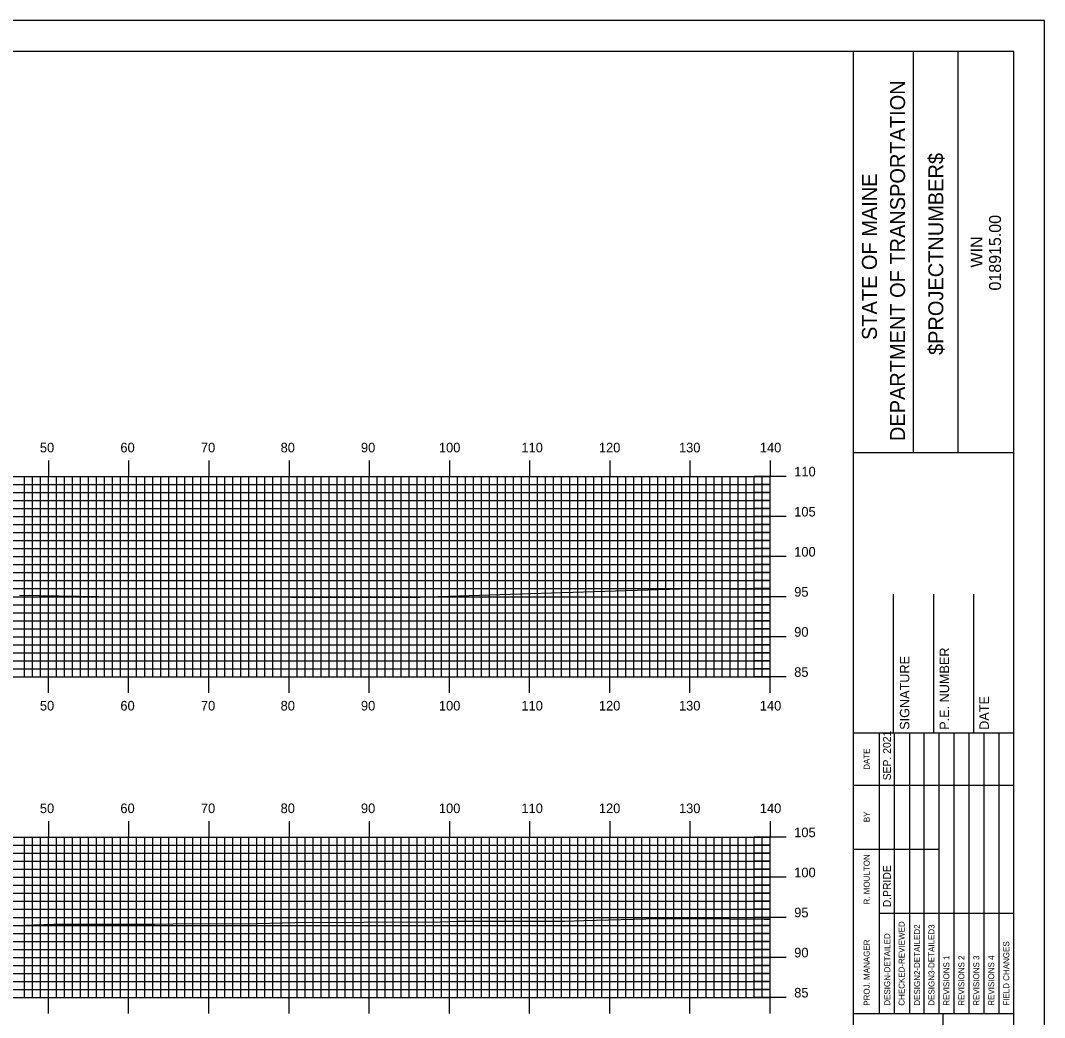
# Model space of a CAD drawing. Extents: x 1764152 to 1764495, y 442591 to 442811.
# Drawn here: x 1764364.3 to 1764492, y 442686.2 to 442810.5 of the extents above; entities that cross this region are included whole.
import ezdxf

# ---------------------------------------------------------------- set-up
doc = ezdxf.new("R2010")
doc.units = 0
for name, color, linetype in [('BORDER', 7, 'Continuous'), ('H_V ANNOTATION', 7, 'Continuous'), ('MAJOR', 7, 'Continuous'), ('MINOR', 7, 'Continuous'), ('PLOT BOUNDARY', 7, 'Continuous'), ('S_Roadway_Centerline', 7, 'Continuous')]:
    doc.layers.add(name, color=color, linetype=linetype)

msp = doc.modelspace()

# ---------------------------------------------------------------- linework, layer by layer
at = {"layer": 'BORDER'}
for p, q in [((1764468.23, 442596.67), (1764468.23, 442806.67)), ((1764475.69, 442756.66), (1764475.69, 442806.66)), ((1764481.28, 442756.66), (1764481.28, 442806.66)), ((1764468.23, 442756.65), (1764488.23, 442756.65)), ((1764473.23, 442721.67), (1764473.23, 442738.97)), ((1764478.23, 442721.67), (1764478.23, 442738.97)), ((1764483.23, 442721.67), (1764483.23, 442738.97)), ((1764468.23, 442721.67), (1764488.23, 442721.67)), ((1764468.23, 442686.67), (1764488.23, 442686.67)), ((1764479.41, 442616.67), (1764479.41, 442686.67))]:
    msp.add_line(p, q, dxfattribs=at)
msp.add_lwpolyline([(1764168.23, 442596.67), (1764488.23, 442596.67), (1764488.23, 442806.67), (1764168.23, 442806.67)], close=True, dxfattribs=at)
for points in [[(1764471.46, 442715.17), (1764471.46, 442721.67)], [(1764473.33, 442686.68), (1764473.33, 442721.67)], [(1764475.19, 442721.67), (1764475.19, 442686.68)], [(1764477.05, 442686.68), (1764477.05, 442721.67)], [(1764478.92, 442686.68), (1764478.92, 442721.67)], [(1764480.78, 442686.68), (1764480.78, 442721.67)], [(1764482.64, 442686.68), (1764482.64, 442721.67)], [(1764484.51, 442686.68), (1764484.51, 442721.67)], [(1764486.37, 442686.68), (1764486.37, 442721.67)], [(1764471.46, 442686.68), (1764471.46, 442720.26)], [(1764468.23, 442715.17), (1764488.23, 442715.17)], [(1764468.23, 442707.17), (1764471.46, 442707.17)], [(1764471.46, 442707.17), (1764478.91, 442707.17)], [(1764471.46, 442699.17), (1764488.23, 442699.17)]]:
    msp.add_lwpolyline(points, dxfattribs=at)
at = {"layer": 'MAJOR'}
for p, q in [((1764367.83, 442755.67), (1764367.83, 442753.67)), ((1764377.83, 442755.67), (1764377.83, 442753.67)), ((1764387.83, 442755.67), (1764387.83, 442753.67)), ((1764397.83, 442755.67), (1764397.83, 442753.67)), ((1764407.83, 442755.67), (1764407.83, 442753.67)), ((1764417.83, 442755.67), (1764417.83, 442753.67)), ((1764427.83, 442755.67), (1764427.83, 442753.67)), ((1764437.83, 442755.67), (1764437.83, 442753.67)), ((1764447.83, 442755.67), (1764447.83, 442753.67)), ((1764457.83, 442755.67), (1764457.83, 442753.67)), ((1764177.83, 442753.67), (1764457.83, 442753.67)), ((1764177.83, 442753.67), (1764457.83, 442753.67)), ((1764367.83, 442728.67), (1764367.83, 442753.67)), ((1764377.83, 442728.67), (1764377.83, 442753.67)), ((1764387.83, 442728.67), (1764387.83, 442753.67)), ((1764397.83, 442728.67), (1764397.83, 442753.67)), ((1764407.83, 442728.67), (1764407.83, 442753.67)), ((1764417.83, 442728.67), (1764417.83, 442753.67)), ((1764427.83, 442728.67), (1764427.83, 442753.67)), ((1764437.83, 442728.67), (1764437.83, 442753.67)), ((1764447.83, 442728.67), (1764447.83, 442753.67)), ((1764459.84, 442753.67), (1764455.83, 442753.67)), ((1764457.83, 442728.67), (1764457.83, 442753.67)), ((1764457.83, 442728.67), (1764457.83, 442753.67)), ((1764177.83, 442748.67), (1764457.83, 442748.67)), ((1764459.84, 442748.67), (1764455.83, 442748.67)), ((1764177.83, 442743.67), (1764457.83, 442743.67)), ((1764459.84, 442743.67), (1764455.83, 442743.67)), ((1764177.83, 442738.67), (1764457.83, 442738.67)), ((1764459.84, 442738.67), (1764455.83, 442738.67)), ((1764177.83, 442733.67), (1764457.83, 442733.67)), ((1764459.84, 442733.67), (1764455.83, 442733.67)), ((1764177.83, 442728.67), (1764457.83, 442728.67)), ((1764177.83, 442728.67), (1764457.83, 442728.67)), ((1764367.83, 442726.66), (1764367.83, 442728.67)), ((1764377.83, 442726.66), (1764377.83, 442728.67)), ((1764387.83, 442726.66), (1764387.83, 442728.67)), ((1764397.83, 442726.66), (1764397.83, 442728.67)), ((1764407.83, 442726.66), (1764407.83, 442728.67)), ((1764417.83, 442726.66), (1764417.83, 442728.67)), ((1764427.83, 442726.66), (1764427.83, 442728.67)), ((1764437.83, 442726.66), (1764437.83, 442728.67)), ((1764447.83, 442726.66), (1764447.83, 442728.67)), ((1764459.84, 442728.67), (1764455.83, 442728.67)), ((1764457.83, 442726.66), (1764457.83, 442728.67)), ((1764367.83, 442710.67), (1764367.83, 442708.67)), ((1764377.83, 442710.67), (1764377.83, 442708.67)), ((1764387.83, 442710.67), (1764387.83, 442708.67)), ((1764397.83, 442710.67), (1764397.83, 442708.67)), ((1764407.83, 442710.67), (1764407.83, 442708.67)), ((1764417.83, 442710.67), (1764417.83, 442708.67)), ((1764427.83, 442710.67), (1764427.83, 442708.67)), ((1764437.83, 442710.67), (1764437.83, 442708.67)), ((1764447.83, 442710.67), (1764447.83, 442708.67)), ((1764457.83, 442710.67), (1764457.83, 442708.67)), ((1764177.83, 442708.67), (1764457.83, 442708.67)), ((1764177.83, 442708.67), (1764457.83, 442708.67)), ((1764367.83, 442688.67), (1764367.83, 442708.67)), ((1764377.83, 442688.67), (1764377.83, 442708.67)), ((1764387.83, 442688.67), (1764387.83, 442708.67)), ((1764397.83, 442688.67), (1764397.83, 442708.67)), ((1764407.83, 442688.67), (1764407.83, 442708.67)), ((1764417.83, 442688.67), (1764417.83, 442708.67)), ((1764427.83, 442688.67), (1764427.83, 442708.67)), ((1764437.83, 442688.67), (1764437.83, 442708.67)), ((1764447.83, 442688.67), (1764447.83, 442708.67)), ((1764459.84, 442708.67), (1764455.83, 442708.67)), ((1764457.83, 442688.67), (1764457.83, 442708.67)), ((1764457.83, 442688.67), (1764457.83, 442708.67)), ((1764177.83, 442703.67), (1764457.83, 442703.67)), ((1764459.84, 442703.67), (1764455.83, 442703.67)), ((1764177.83, 442698.67), (1764457.83, 442698.67)), ((1764459.84, 442698.67), (1764455.83, 442698.67)), ((1764177.83, 442693.67), (1764457.83, 442693.67)), ((1764459.84, 442693.67), (1764455.83, 442693.67)), ((1764177.83, 442688.67), (1764457.83, 442688.67)), ((1764177.83, 442688.67), (1764457.83, 442688.67)), ((1764367.83, 442686.66), (1764367.83, 442688.67)), ((1764377.83, 442686.66), (1764377.83, 442688.67)), ((1764387.83, 442686.66), (1764387.83, 442688.67)), ((1764397.83, 442686.66), (1764397.83, 442688.67)), ((1764407.83, 442686.66), (1764407.83, 442688.67)), ((1764417.83, 442686.66), (1764417.83, 442688.67)), ((1764427.83, 442686.66), (1764427.83, 442688.67)), ((1764437.83, 442686.66), (1764437.83, 442688.67)), ((1764447.83, 442686.66), (1764447.83, 442688.67)), ((1764459.84, 442688.67), (1764455.83, 442688.67)), ((1764457.83, 442686.66), (1764457.83, 442688.67))]:
    msp.add_line(p, q, dxfattribs=at)
at = {"layer": 'MINOR'}
for p, q in [((1764364.83, 442728.67), (1764364.83, 442753.67)), ((1764365.83, 442728.67), (1764365.83, 442753.67)), ((1764366.83, 442728.67), (1764366.83, 442753.67)), ((1764368.83, 442728.67), (1764368.83, 442753.67)), ((1764369.83, 442728.67), (1764369.83, 442753.67)), ((1764370.83, 442728.67), (1764370.83, 442753.67)), ((1764371.83, 442728.67), (1764371.83, 442753.67)), ((1764372.83, 442728.67), (1764372.83, 442753.67)), ((1764373.83, 442728.67), (1764373.83, 442753.67)), ((1764374.83, 442728.67), (1764374.83, 442753.67)), ((1764375.83, 442728.67), (1764375.83, 442753.67)), ((1764376.83, 442728.67), (1764376.83, 442753.67)), ((1764378.83, 442728.67), (1764378.83, 442753.67)), ((1764379.83, 442728.67), (1764379.83, 442753.67)), ((1764380.83, 442728.67), (1764380.83, 442753.67)), ((1764381.83, 442728.67), (1764381.83, 442753.67)), ((1764382.83, 442728.67), (1764382.83, 442753.67)), ((1764383.83, 442728.67), (1764383.83, 442753.67)), ((1764384.83, 442728.67), (1764384.83, 442753.67)), ((1764385.83, 442728.67), (1764385.83, 442753.67)), ((1764386.83, 442728.67), (1764386.83, 442753.67)), ((1764388.83, 442728.67), (1764388.83, 442753.67)), ((1764389.83, 442728.67), (1764389.83, 442753.67)), ((1764390.83, 442728.67), (1764390.83, 442753.67)), ((1764391.83, 442728.67), (1764391.83, 442753.67)), ((1764392.83, 442728.67), (1764392.83, 442753.67)), ((1764393.83, 442728.67), (1764393.83, 442753.67)), ((1764394.83, 442728.67), (1764394.83, 442753.67)), ((1764395.83, 442728.67), (1764395.83, 442753.67)), ((1764396.83, 442728.67), (1764396.83, 442753.67)), ((1764398.83, 442728.67), (1764398.83, 442753.67)), ((1764399.83, 442728.67), (1764399.83, 442753.67)), ((1764400.83, 442728.67), (1764400.83, 442753.67)), ((1764401.83, 442728.67), (1764401.83, 442753.67)), ((1764402.83, 442728.67), (1764402.83, 442753.67)), ((1764403.83, 442728.67), (1764403.83, 442753.67)), ((1764404.83, 442728.67), (1764404.83, 442753.67)), ((1764405.83, 442728.67), (1764405.83, 442753.67)), ((1764406.83, 442728.67), (1764406.83, 442753.67)), ((1764408.83, 442728.67), (1764408.83, 442753.67)), ((1764409.83, 442728.67), (1764409.83, 442753.67)), ((1764410.83, 442728.67), (1764410.83, 442753.67)), ((1764411.83, 442728.67), (1764411.83, 442753.67)), ((1764412.83, 442728.67), (1764412.83, 442753.67)), ((1764413.83, 442728.67), (1764413.83, 442753.67)), ((1764414.83, 442728.67), (1764414.83, 442753.67)), ((1764415.83, 442728.67), (1764415.83, 442753.67)), ((1764416.83, 442728.67), (1764416.83, 442753.67)), ((1764418.83, 442728.67), (1764418.83, 442753.67)), ((1764419.83, 442728.67), (1764419.83, 442753.67)), ((1764420.83, 442728.67), (1764420.83, 442753.67)), ((1764421.83, 442728.67), (1764421.83, 442753.67)), ((1764422.83, 442728.67), (1764422.83, 442753.67)), ((1764423.83, 442728.67), (1764423.83, 442753.67)), ((1764424.83, 442728.67), (1764424.83, 442753.67)), ((1764425.83, 442728.67), (1764425.83, 442753.67)), ((1764426.83, 442728.67), (1764426.83, 442753.67)), ((1764428.83, 442728.67), (1764428.83, 442753.67)), ((1764429.83, 442728.67), (1764429.83, 442753.67)), ((1764430.83, 442728.67), (1764430.83, 442753.67)), ((1764431.83, 442728.67), (1764431.83, 442753.67)), ((1764432.83, 442728.67), (1764432.83, 442753.67)), ((1764433.83, 442728.67), (1764433.83, 442753.67)), ((1764434.83, 442728.67), (1764434.83, 442753.67)), ((1764435.83, 442728.67), (1764435.83, 442753.67)), ((1764436.83, 442728.67), (1764436.83, 442753.67)), ((1764438.83, 442728.67), (1764438.83, 442753.67)), ((1764439.83, 442728.67), (1764439.83, 442753.67)), ((1764440.83, 442728.67), (1764440.83, 442753.67)), ((1764441.83, 442728.67), (1764441.83, 442753.67)), ((1764442.83, 442728.67), (1764442.83, 442753.67)), ((1764443.83, 442728.67), (1764443.83, 442753.67)), ((1764444.83, 442728.67), (1764444.83, 442753.67)), ((1764445.83, 442728.67), (1764445.83, 442753.67)), ((1764446.83, 442728.67), (1764446.83, 442753.67)), ((1764448.83, 442728.67), (1764448.83, 442753.67)), ((1764449.83, 442728.67), (1764449.83, 442753.67)), ((1764450.83, 442728.67), (1764450.83, 442753.67)), ((1764451.83, 442728.67), (1764451.83, 442753.67)), ((1764452.83, 442728.67), (1764452.83, 442753.67)), ((1764453.83, 442728.67), (1764453.83, 442753.67)), ((1764454.83, 442728.67), (1764454.83, 442753.67)), ((1764455.83, 442728.67), (1764455.83, 442753.67)), ((1764456.83, 442728.67), (1764456.83, 442753.67)), ((1764177.83, 442752.67), (1764457.83, 442752.67)), ((1764177.83, 442751.67), (1764457.83, 442751.67)), ((1764457.83, 442752.67), (1764455.83, 442752.67)), ((1764457.83, 442751.67), (1764455.83, 442751.67)), ((1764177.83, 442750.67), (1764457.83, 442750.67)), ((1764457.83, 442750.67), (1764455.83, 442750.67)), ((1764177.83, 442749.67), (1764457.83, 442749.67)), ((1764457.83, 442749.67), (1764455.83, 442749.67)), ((1764177.83, 442747.67), (1764457.83, 442747.67)), ((1764177.83, 442746.67), (1764457.83, 442746.67)), ((1764457.83, 442747.67), (1764455.83, 442747.67)), ((1764457.83, 442746.67), (1764455.83, 442746.67)), ((1764177.83, 442745.67), (1764457.83, 442745.67)), ((1764457.83, 442745.67), (1764455.83, 442745.67)), ((1764177.83, 442744.67), (1764457.83, 442744.67)), ((1764457.83, 442744.67), (1764455.83, 442744.67)), ((1764177.83, 442742.67), (1764457.83, 442742.67)), ((1764457.83, 442742.67), (1764455.83, 442742.67)), ((1764177.83, 442741.67), (1764457.83, 442741.67)), ((1764457.83, 442741.67), (1764455.83, 442741.67)), ((1764177.83, 442740.67), (1764457.83, 442740.67)), ((1764457.83, 442740.67), (1764455.83, 442740.67)), ((1764177.83, 442739.67), (1764457.83, 442739.67)), ((1764457.83, 442739.67), (1764455.83, 442739.67)), ((1764177.83, 442737.67), (1764457.83, 442737.67)), ((1764457.83, 442737.67), (1764455.83, 442737.67)), ((1764177.83, 442736.67), (1764457.83, 442736.67)), ((1764457.83, 442736.67), (1764455.83, 442736.67)), ((1764177.83, 442735.67), (1764457.83, 442735.67)), ((1764457.83, 442735.67), (1764455.83, 442735.67)), ((1764177.83, 442734.67), (1764457.83, 442734.67)), ((1764457.83, 442734.67), (1764455.83, 442734.67)), ((1764177.83, 442732.67), (1764457.83, 442732.67)), ((1764457.83, 442732.67), (1764455.83, 442732.67)), ((1764177.83, 442731.67), (1764457.83, 442731.67)), ((1764457.83, 442731.67), (1764455.83, 442731.67)), ((1764177.83, 442730.67), (1764457.83, 442730.67)), ((1764457.83, 442730.67), (1764455.83, 442730.67)), ((1764177.83, 442729.67), (1764457.83, 442729.67)), ((1764457.83, 442729.67), (1764455.83, 442729.67)), ((1764364.83, 442688.67), (1764364.83, 442708.67)), ((1764365.83, 442688.67), (1764365.83, 442708.67)), ((1764366.83, 442688.67), (1764366.83, 442708.67)), ((1764368.83, 442688.67), (1764368.83, 442708.67)), ((1764369.83, 442688.67), (1764369.83, 442708.67)), ((1764370.83, 442688.67), (1764370.83, 442708.67)), ((1764371.83, 442688.67), (1764371.83, 442708.67)), ((1764372.83, 442688.67), (1764372.83, 442708.67)), ((1764373.83, 442688.67), (1764373.83, 442708.67)), ((1764374.83, 442688.67), (1764374.83, 442708.67)), ((1764375.83, 442688.67), (1764375.83, 442708.67)), ((1764376.83, 442688.67), (1764376.83, 442708.67)), ((1764378.83, 442688.67), (1764378.83, 442708.67)), ((1764379.83, 442688.67), (1764379.83, 442708.67)), ((1764380.83, 442688.67), (1764380.83, 442708.67)), ((1764381.83, 442688.67), (1764381.83, 442708.67)), ((1764382.83, 442688.67), (1764382.83, 442708.67)), ((1764383.83, 442688.67), (1764383.83, 442708.67)), ((1764384.83, 442688.67), (1764384.83, 442708.67)), ((1764385.83, 442688.67), (1764385.83, 442708.67)), ((1764386.83, 442688.67), (1764386.83, 442708.67)), ((1764388.83, 442688.67), (1764388.83, 442708.67)), ((1764389.83, 442688.67), (1764389.83, 442708.67)), ((1764390.83, 442688.67), (1764390.83, 442708.67)), ((1764391.83, 442688.67), (1764391.83, 442708.67)), ((1764392.83, 442688.67), (1764392.83, 442708.67)), ((1764393.83, 442688.67), (1764393.83, 442708.67)), ((1764394.83, 442688.67), (1764394.83, 442708.67)), ((1764395.83, 442688.67), (1764395.83, 442708.67)), ((1764396.83, 442688.67), (1764396.83, 442708.67)), ((1764398.83, 442688.67), (1764398.83, 442708.67)), ((1764399.83, 442688.67), (1764399.83, 442708.67)), ((1764400.83, 442688.67), (1764400.83, 442708.67)), ((1764401.83, 442688.67), (1764401.83, 442708.67)), ((1764402.83, 442688.67), (1764402.83, 442708.67)), ((1764403.83, 442688.67), (1764403.83, 442708.67)), ((1764404.83, 442688.67), (1764404.83, 442708.67)), ((1764405.83, 442688.67), (1764405.83, 442708.67)), ((1764406.83, 442688.67), (1764406.83, 442708.67)), ((1764408.83, 442688.67), (1764408.83, 442708.67)), ((1764409.83, 442688.67), (1764409.83, 442708.67)), ((1764410.83, 442688.67), (1764410.83, 442708.67)), ((1764411.83, 442688.67), (1764411.83, 442708.67)), ((1764412.83, 442688.67), (1764412.83, 442708.67)), ((1764413.83, 442688.67), (1764413.83, 442708.67)), ((1764414.83, 442688.67), (1764414.83, 442708.67)), ((1764415.83, 442688.67), (1764415.83, 442708.67)), ((1764416.83, 442688.67), (1764416.83, 442708.67)), ((1764418.83, 442688.67), (1764418.83, 442708.67)), ((1764419.83, 442688.67), (1764419.83, 442708.67)), ((1764420.83, 442688.67), (1764420.83, 442708.67)), ((1764421.83, 442688.67), (1764421.83, 442708.67)), ((1764422.83, 442688.67), (1764422.83, 442708.67)), ((1764423.83, 442688.67), (1764423.83, 442708.67)), ((1764424.83, 442688.67), (1764424.83, 442708.67)), ((1764425.83, 442688.67), (1764425.83, 442708.67)), ((1764426.83, 442688.67), (1764426.83, 442708.67)), ((1764428.83, 442688.67), (1764428.83, 442708.67)), ((1764429.83, 442688.67), (1764429.83, 442708.67)), ((1764430.83, 442688.67), (1764430.83, 442708.67)), ((1764431.83, 442688.67), (1764431.83, 442708.67)), ((1764432.83, 442688.67), (1764432.83, 442708.67)), ((1764433.83, 442688.67), (1764433.83, 442708.67)), ((1764434.83, 442688.67), (1764434.83, 442708.67)), ((1764435.83, 442688.67), (1764435.83, 442708.67)), ((1764436.83, 442688.67), (1764436.83, 442708.67)), ((1764438.83, 442688.67), (1764438.83, 442708.67)), ((1764439.83, 442688.67), (1764439.83, 442708.67)), ((1764440.83, 442688.67), (1764440.83, 442708.67)), ((1764441.83, 442688.67), (1764441.83, 442708.67)), ((1764442.83, 442688.67), (1764442.83, 442708.67)), ((1764443.83, 442688.67), (1764443.83, 442708.67)), ((1764444.83, 442688.67), (1764444.83, 442708.67)), ((1764445.83, 442688.67), (1764445.83, 442708.67)), ((1764446.83, 442688.67), (1764446.83, 442708.67)), ((1764448.83, 442688.67), (1764448.83, 442708.67)), ((1764449.83, 442688.67), (1764449.83, 442708.67)), ((1764450.83, 442688.67), (1764450.83, 442708.67)), ((1764451.83, 442688.67), (1764451.83, 442708.67)), ((1764452.83, 442688.67), (1764452.83, 442708.67)), ((1764453.83, 442688.67), (1764453.83, 442708.67)), ((1764454.83, 442688.67), (1764454.83, 442708.67)), ((1764455.83, 442688.67), (1764455.83, 442708.67)), ((1764456.83, 442688.67), (1764456.83, 442708.67)), ((1764177.83, 442707.67), (1764457.83, 442707.67)), ((1764457.83, 442707.67), (1764455.83, 442707.67)), ((1764177.83, 442706.67), (1764457.83, 442706.67)), ((1764177.83, 442705.67), (1764457.83, 442705.67)), ((1764457.83, 442706.67), (1764455.83, 442706.67)), ((1764457.83, 442705.67), (1764455.83, 442705.67)), ((1764177.83, 442704.67), (1764457.83, 442704.67)), ((1764457.83, 442704.67), (1764455.83, 442704.67)), ((1764177.83, 442702.67), (1764457.83, 442702.67)), ((1764457.83, 442702.67), (1764455.83, 442702.67)), ((1764177.83, 442701.67), (1764457.83, 442701.67)), ((1764177.83, 442700.67), (1764457.83, 442700.67)), ((1764457.83, 442701.67), (1764455.83, 442701.67)), ((1764457.83, 442700.67), (1764455.83, 442700.67)), ((1764177.83, 442699.67), (1764457.83, 442699.67)), ((1764457.83, 442699.67), (1764455.83, 442699.67)), ((1764177.83, 442697.67), (1764457.83, 442697.67)), ((1764177.83, 442696.67), (1764457.83, 442696.67)), ((1764457.83, 442697.67), (1764455.83, 442697.67)), ((1764457.83, 442696.67), (1764455.83, 442696.67)), ((1764177.83, 442695.67), (1764457.83, 442695.67)), ((1764457.83, 442695.67), (1764455.83, 442695.67)), ((1764177.83, 442694.67), (1764457.83, 442694.67)), ((1764457.83, 442694.67), (1764455.83, 442694.67)), ((1764177.83, 442692.67), (1764457.83, 442692.67)), ((1764177.83, 442691.67), (1764457.83, 442691.67)), ((1764457.83, 442692.67), (1764455.83, 442692.67)), ((1764457.83, 442691.67), (1764455.83, 442691.67)), ((1764177.83, 442690.67), (1764457.83, 442690.67)), ((1764457.83, 442690.67), (1764455.83, 442690.67)), ((1764177.83, 442689.67), (1764457.83, 442689.67)), ((1764457.83, 442689.67), (1764455.83, 442689.67))]:
    msp.add_line(p, q, dxfattribs=at)
at = {"layer": 'PLOT BOUNDARY'}
msp.add_lwpolyline([(1764152.04, 442590.55), (1764492.04, 442590.55), (1764492.04, 442810.55), (1764152.04, 442810.55)], close=True, dxfattribs=at)
at = {"layer": 'S_Roadway_Centerline'}
for points in [[(1764364.2, 442738.84), (1764376.54, 442738.65), (1764377.74, 442738.63), (1764378.57, 442738.63), (1764394.67, 442738.63), (1764401.57, 442738.57), (1764413.29, 442738.62), (1764414.23, 442738.62), (1764416.44, 442738.7), (1764430.57, 442739.17), (1764438.53, 442739.41), (1764447.94, 442739.67), (1764457.83, 442739.62)], [(1764362.25, 442697.61), (1764368.48, 442697.83), (1764379.96, 442697.81), (1764381.04, 442697.83), (1764383.35, 442697.85), (1764393.88, 442697.92), (1764398.55, 442698.03), (1764407.14, 442698.05), (1764416.66, 442698.12), (1764418.94, 442698.21), (1764425.56, 442698.21), (1764432.21, 442698.21), (1764434.61, 442698.29), (1764443.87, 442698.51), (1764452.87, 442698.49), (1764457.08, 442698.45), (1764457.83, 442698.46)]]:
    msp.add_lwpolyline(points, dxfattribs=at)

# ---------------------------------------------------------------- texts
at = {"layer": 'BORDER'}
for s, height, p in [('DEPARTMENT OF TRANSPORTATION', 1.8635, (1764474.65, 442758.08)), ('$PROJECTNUMBER$', 1.8635, (1764479.42, 442768.82)), ('STATE OF MAINE', 1.8635, (1764471.14, 442770.69)), ('018915.00', 1.491, (1764486.62, 442776.86)), ('WIN', 1.491, (1764484.31, 442779.73)), ('SIGNATURE', 1.181, (1764475.19, 442722.06)), ('P.E. NUMBER', 1.1811, (1764480.15, 442722.06)), ('DATE', 1.181, (1764485.11, 442722.06)), ('SEP. 2021', 0.969, (1764472.88, 442715.76)), ('DATE', 0.743, (1764470.24, 442717.08)), ('BY', 0.743, (1764470.24, 442710.54)), ('R. MOULTON', 0.745, (1764470.24, 442700.28)), ('D.PRIDE', 0.969, (1764472.88, 442699.92)), ('CHECKED-REVIEWED', 0.7455, (1764474.59, 442687.65)), ('DESIGN2-DETAILED2', 0.7455, (1764476.53, 442687.65)), ('DESIGN3-DETAILED3', 0.7455, (1764478.32, 442687.65)), ('PROJ. MANAGER', 0.7455, (1764470.24, 442687.65)), ('DESIGN-DETAILED', 0.7455, (1764472.8, 442687.65)), ('FIELD CHANGES', 0.7455, (1764487.64, 442687.65)), ('REVISIONS 1', 0.7455, (1764480.18, 442687.65)), ('REVISIONS 2', 0.7455, (1764482.05, 442687.65)), ('REVISIONS 3', 0.7455, (1764483.91, 442687.65)), ('REVISIONS 4', 0.7455, (1764485.77, 442687.65))]:
    msp.add_text(s, height=height, rotation=90, dxfattribs=at).set_placement(p)
at = {"layer": 'H_V ANNOTATION'}
for s, p in [('50', (1764366.76, 442756.67)), ('60', (1764376.8, 442756.67)), ('70', (1764386.84, 442756.67)), ('80', (1764396.78, 442756.67)), ('90', (1764406.8, 442756.67)), ('100', (1764416.52, 442756.67)), ('110', (1764426.81, 442756.67)), ('120', (1764436.47, 442756.67)), ('130', (1764446.46, 442756.67)), ('140', (1764456.54, 442756.67)), ('110', (1764460.83, 442753.67)), ('105', (1764460.83, 442748.67)), ('100', (1764460.83, 442743.67)), ('95', (1764460.83, 442738.67)), ('90', (1764460.83, 442733.67)), ('85', (1764460.83, 442728.67)), ('50', (1764366.76, 442724.47)), ('60', (1764376.8, 442724.47)), ('70', (1764386.84, 442724.47)), ('80', (1764396.78, 442724.47)), ('90', (1764406.8, 442724.47)), ('100', (1764416.52, 442724.47)), ('110', (1764426.81, 442724.47)), ('120', (1764436.47, 442724.47)), ('130', (1764446.46, 442724.47)), ('140', (1764456.54, 442724.47)), ('50', (1764366.76, 442711.67)), ('60', (1764376.8, 442711.67)), ('70', (1764386.84, 442711.67)), ('80', (1764396.78, 442711.67)), ('90', (1764406.8, 442711.67)), ('100', (1764416.52, 442711.67)), ('110', (1764426.81, 442711.67)), ('120', (1764436.47, 442711.67)), ('130', (1764446.46, 442711.67)), ('140', (1764456.54, 442711.67)), ('105', (1764460.83, 442708.67)), ('100', (1764460.83, 442703.67)), ('95', (1764460.83, 442698.67)), ('90', (1764460.83, 442693.67)), ('85', (1764460.83, 442688.67))]:
    msp.add_text(s, height=1.2, dxfattribs=at).set_placement(p)

doc.saveas('drawing.dxf')
